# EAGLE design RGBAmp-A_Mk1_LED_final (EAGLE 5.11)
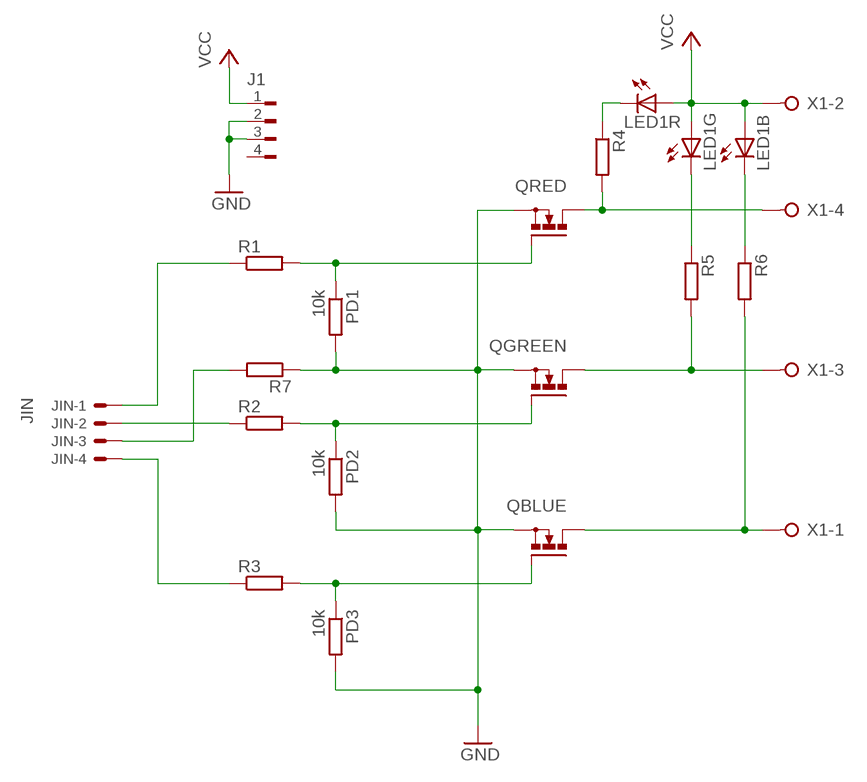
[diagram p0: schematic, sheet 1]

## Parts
J1  FLOPPY-4  [FLOPPY-4]
JIN  JIN  22--04  [6410-04A]
LED1  MULTILED_LRTB_G6TG  [P-LCC-6_TOPLED]
PD1  10k  R-EU_0207/5V  [0207/5V]
PD2  10k  R-EU_0207/10  [0207/10]
PD3  10k  R-EU_0207/2V  [0207/2V]
QBLUE  PMOSFET_NTO220BV  [TO220BV]
QGREEN  PMOSFET_NTO220BV  [TO220BV]
QRED  PMOSFET_NTO220BV  [TO220BV]
R1  R-EU_0207/15  [0207/15]
R2  R-EU_0207/10  [0207/10]
R3  R-EU_0204/7  [0204/7]
R4  R-EU_0207/10  [0207/10]
R5  R-EU_0207/10  [0207/10]
R6  R-EU_0207/15  [0207/15]
R7  R-EU_0207/5V  [0207/5V]
X1  W237-04P  [W237-4P]

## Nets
GND: J1.2 J1.3 PD1.2 PD2.2 PD3.2 QBLUE.S QGREEN.S QRED.S R7.1
N$1: PD1.1 QRED.G R1.2
N$2: PD2.1 QGREEN.G R2.2
N$3: PD3.1 QBLUE.G R3.2
N$4: JIN.4 R3.1
N$5: JIN.2 R2.1
N$6: JIN.1 R1.1
N$7: QRED.D R4.2 X1.4
N$8: QGREEN.D R5.2 X1.3
N$9: QBLUE.D R6.2 X1.1
N$10: LED1.C1(R:C) R4.1
N$11: LED1.C2(G:C) R5.1
N$12: LED1.C3(B:C) R6.1
N$13: JIN.3 R7.2
VCC: J1.1 LED1.A1(R:A) LED1.A2(G:A) LED1.A3(B:A) X1.2
Unconnected: J1.4

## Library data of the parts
J1 = con-amp:FLOPPY-4: MATE N-LOCK Floppy / HDD conector Distributor: Bürklin 71F970; OC_FARNELL: unknown; OC_NEWARK: unknown
JIN = con-molex:22-?-04: CONNECTOR wire to board 2.54 mm (.1 inch) pitch header
LED1 = led:MULTILED_LRTB_G6TG: 6-lead MULTILED® Enhanced optical Power LED (ThinFilm® / ThinGaN®) Source. OSRAM - LRTB_G6TG.pdf
PD1-PD3 = resistor:R-EU_: RESISTOR, European symbol
QBLUE QGREEN QRED = transistor-power:PMOSFET_N: Power MOSFET N-Channel
R1-R7 = rcl:R-EU_: RESISTOR, European symbol
X1 = con-wago-508:W237-04P: WAGO SREW CLAMP; OC_FARNELL: unknown; OC_NEWARK: unknown

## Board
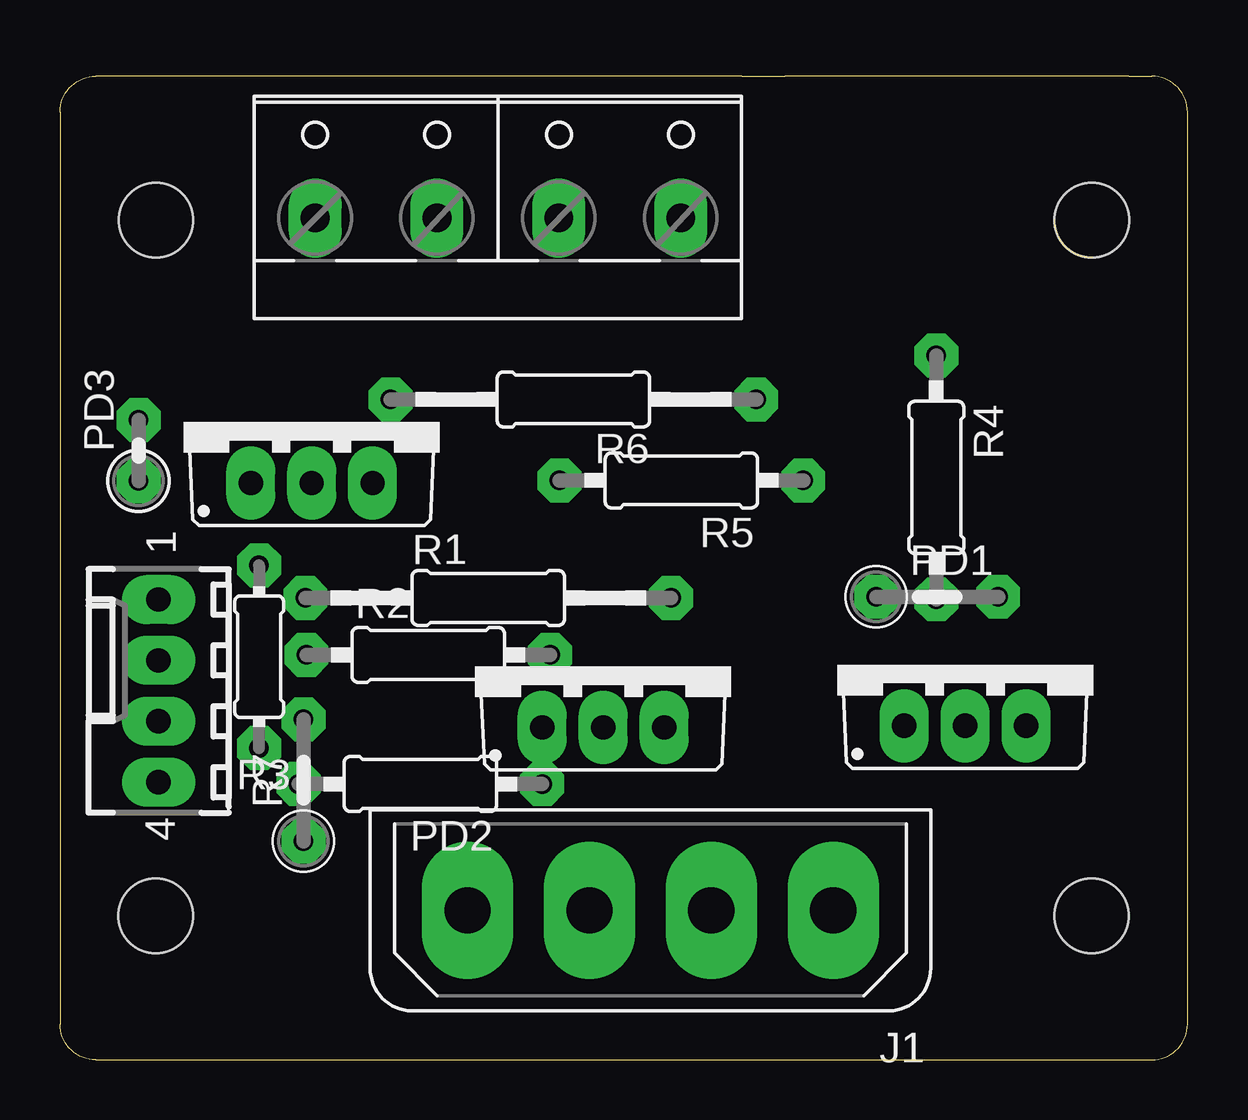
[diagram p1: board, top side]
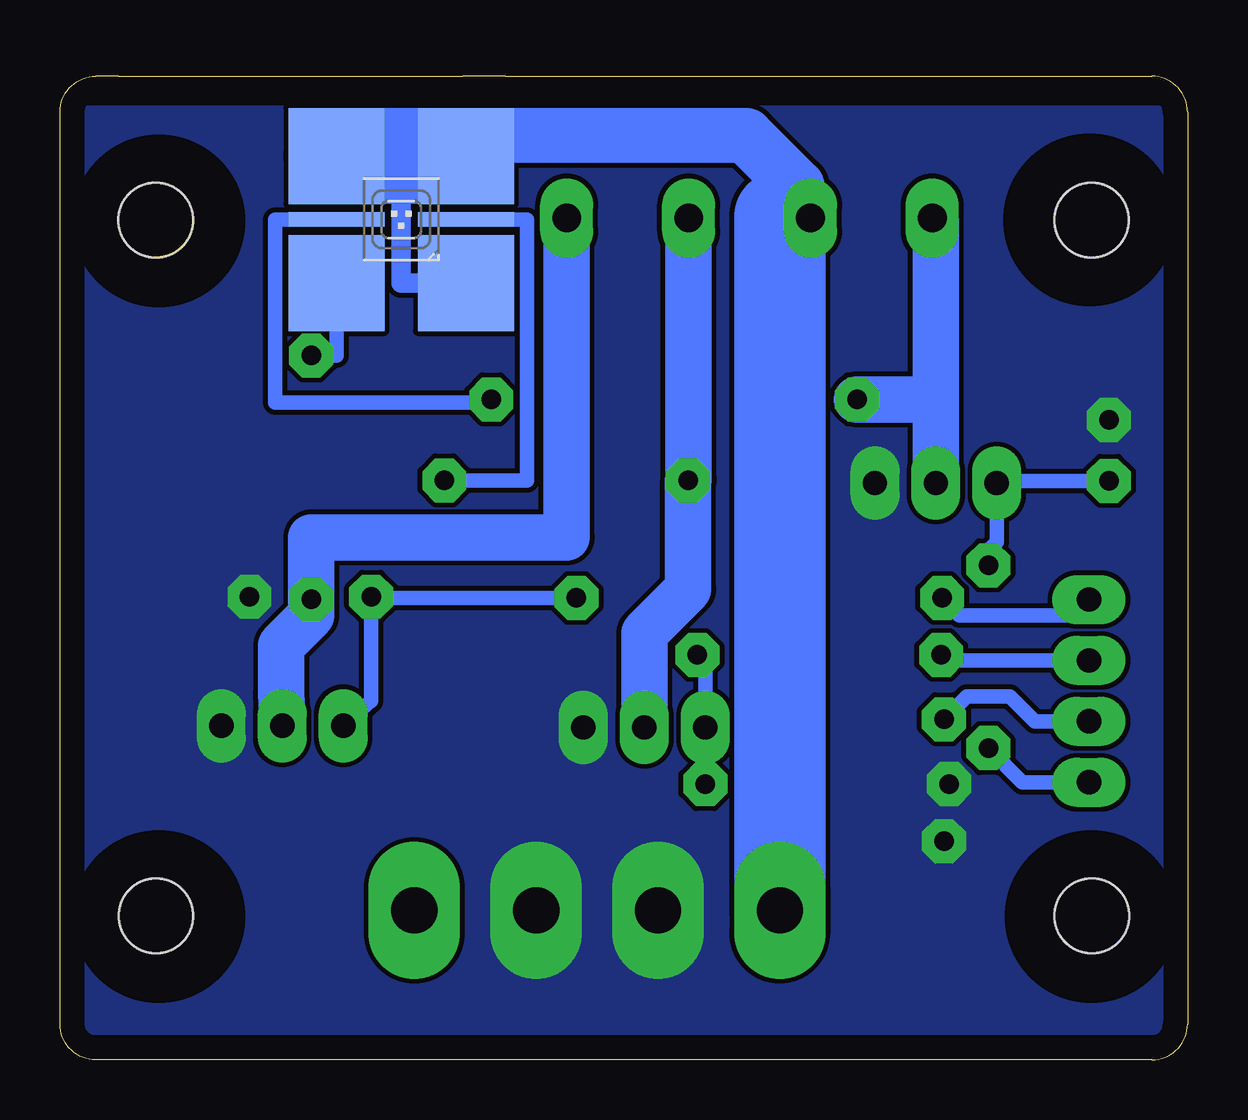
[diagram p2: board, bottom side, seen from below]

Size 47 x 41 mm. Coordinates in mm from the lower left corner, seen from the top.
Outline: 41.44,35.03 arc90 43.02,33.45 43.03,33.45
Outline: 44.55,41 45.51,41 arc-90 47,39.51 47,1.49 arc-90 45.51,0 1.49,0 arc-90 0,1.49 0,39.51 arc-90 1.49,41 28.43,41 30.21,41 44.55,41
Copper layers (1*16): Top 0.035mm / dielectric 1.5mm / Bottom 0.035mm
Design rules "default *": minimum track width 10mil, minimum drill 12mil, track to track 8mil, track to pad 8mil, pad to pad 8mil, via to via 8mil, smd to smd 8mil, copper to edge 40mil, drill to drill 8mil, minimum pad ring 20mil, minimum via ring 8mil, stop-mask expansion 4mil, vias tented up to drill 0mil, thermal gap 10mil
Holes 3.1 mm at 43,6.01 3.99,6 4,35 43.01,35
bKeepout: area 0.5,31.4 to 7.7,38.6; area 0.4,2.4 to 7.6,9.6; area 39.3,2.4 to 46.5,9.6; area 39.3,31.4 to 46.5,38.6
tRestrict: area 0.5,31.4 to 7.7,38.6; area 0.4,2.4 to 7.6,9.6; area 39.3,2.4 to 46.5,9.6; area 39.3,31.4 to 46.5,38.6
bRestrict: area 0.5,31.4 to 7.7,38.6; area 0.4,2.4 to 7.6,9.6; area 39.3,2.4 to 46.5,9.6; area 39.3,31.4 to 46.5,38.6

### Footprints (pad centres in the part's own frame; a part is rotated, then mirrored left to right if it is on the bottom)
FLOPPY-4 = drill 1.93 pad 3.81 long: 1 7.62,0; 2 2.54,0; 3 -2.54,0; 4 -7.62,0
6410-04A = drill 1.016 long: 1 3.81,0; 2 1.27,0; 3 -1.27,0; 4 -3.81,0
P-LCC-6_TOPLED = smd 4 x 4: A1 -2.65,-2.7; A2 2.65,-2.7; A3 2.65,2.7; C1 -2.65,2.7 | smd 0.6 x 4: C2 0,-2.7; C3 0,2.7
0207/5V = drill 0.813 octagon: 1 -2.54,0; 2 2.54,0
0207/10 = drill 0.813 octagon: 1 -5.08,0; 2 5.08,0
0207/2V = drill 0.813 octagon: 1 -1.27,0; 2 1.27,0
TO220BV = drill 1.016 long: D 0,-2.54; G -2.54,-2.54; S 2.54,-2.54
0207/15 = drill 0.813 octagon: 1 -7.62,0; 2 7.62,0
0204/7 = drill 0.813 octagon: 1 -3.81,0; 2 3.81,0
W237-4P = drill 1.194 long: 1 -7.62,-0.635; 2 -2.54,-0.635; 3 2.54,-0.635; 4 7.62,-0.635

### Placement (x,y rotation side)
J1  24.61,6.23 180 top
JIN  4.11,15.38 90 top
LED1  32.78,35.03 90 bottom
PD1  36.57,19.3 0 top
PD2  15.02,11.5 180 top
PD3  3.28,25.4 90 top
QBLUE  10.49,26.58 0 top
QGREEN  22.64,16.39 0 top
QRED  37.73,16.46 0 top
R1  17.85,19.25 0 top
R2  15.35,16.88 0 top
R3  8.3,16.8 90 top
R4  36.53,24.28 270 top
R5  25.9,24.15 180 top
R6  21.4,27.53 180 top
R7  10.15,11.65 90 top
X1  18.26,35.72 0 top

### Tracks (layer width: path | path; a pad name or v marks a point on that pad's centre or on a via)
GND
  pour Bottom (no thermals): 0.03,39.53 1.15,39.78 47.03,39.78 47.03,1.53 45.53,0.03 1.53,0.03 0.03,1.53
N$1
  Bottom 0.61: R1.2 33.98,19.25 PD1.1 34.03,14.96 QRED.G
N$2
  Bottom 0.61: PD2.1 QGREEN.G 20.1,16.55 R2.2
N$3
  Bottom 0.61: PD3.1 7.86,24.13 QBLUE.G 7.95,21.59 8.93,20.61 R3.2
N$4
  Bottom 0.61: JIN.4 6.88,11.57 R3.1
N$5
  Bottom 0.61: JIN.2 10.04,16.65 R2.1
N$6
  Bottom 0.61: JIN.1 4.77,18.53 9.51,18.53 R1.1
N$7
  Bottom 1.93: 37.78,15.42 QRED.D 37.78,15.47 37.78,17.28 36.53,18.53 R4.2 36.53,21.78 25.88,21.78 X1.4
N$8
  Bottom 1.93: QGREEN.D 22.64,17.79 20.82,19.61 R5.2 20.8,24.18 X1.3
N$9
  Bottom 1.93: QBLUE.D 10.49,27.53 | 10.49,27.53 10.49,34.94 X1.1 | 10.49,27.53 R6.2
N$10
  Bottom 0.61: R4.1 35.48,29.36 LED1.C1
N$11
  Bottom 0.61: LED1.C2 27.53,35.03 27.53,24.15 R5.1
N$12
  Bottom 0.61: LED1.C3 38.03,35.03 38.03,27.4 29.15,27.4 R6.1
N$13
  Bottom 0.61: JIN.3 6.36,14.11 7.4,15.15 9.19,15.15 R7.2
VCC
  Bottom 0.813: LED1.A1 32.78,32.38 32.78,37.68
  Bottom 1.016: 16.9,35.15 16.65,34.9 16.28,34.9 | X1.2 15.78,35.03 16.28,35.03
  Bottom 2.3: LED1.A2 29.23,38.53 18.4,38.53 16.28,36.4 16.28,35.03 16.28,34.9 16.28,34.4
  Bottom 3.81: J1.1 16.99,35.15 16.9,35.15
  Bottom 4: LED1.A2 32.78,37.68 LED1.A3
